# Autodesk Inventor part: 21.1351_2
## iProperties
Created: 2006-12
Part Number: 21.1351_2
Document SubType Name: Modeling
Designer: Andy Moles
Material: Steel, Mild
Density: 7.86 g/cm^3
Mass: 4.25424 g
Surface Area: 8.34272 cm^2
Volume: 0.541252 cm^3
Description: M8 SQUARE NUT POS FXG
Author: Andy Moles
Title: M8 SQUARE NUT POS FXG
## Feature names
1. Extrusion1
2. Revolution1
3. Fillet2
4. Extrusion3
